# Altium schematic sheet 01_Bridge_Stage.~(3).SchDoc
size A4; SheetNumber: 3; SheetTotal: 3
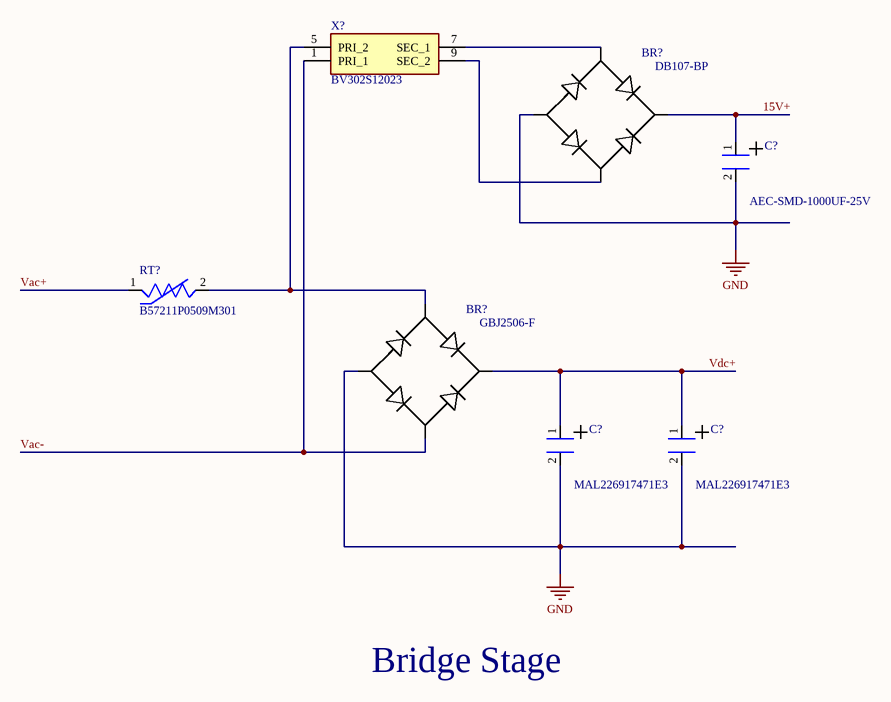
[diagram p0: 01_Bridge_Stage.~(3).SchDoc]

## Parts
(Parts that share a designator on the sheet are numbered #1, #2 ... from top to bottom, then left to right.)
BR?#1  DB107-BP  [898_DB107-BP]
BR?#2  GBJ2506-F  [996_GBJ_1]
C?#1  AEC-SMD-1000UF-25V  [098_AEC-SMD-1000UF-25V]
C?#2  MAL226917471E3  [099_MAL226917471E3]
C?#3  MAL226917471E3  [099_MAL226917471E3]
RT?  B57211P0509M301  [307_THRMRB750W80L1300T600H2000]
X?  BV302S12023  [899_BV302S12023]

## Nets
GND: BR?#1.2 BR?#2.4 C?#1.2 C?#2.2 C?#3.2
15V+: BR?#1.1 C?#1.1
Vac+: RT?.1
Vac-: BR?#2.3 X?.1(PRI_1)
Vdc+: BR?#2.1 C?#2.1 C?#3.1
NetBR?#1_3: BR?#1.3 X?.7(SEC_1)
NetBR?#1_4: BR?#1.4 X?.9(SEC_2)
NetBR?#2_2: BR?#2.2 RT?.2 X?.5(PRI_2)

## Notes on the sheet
- Bridge Stage

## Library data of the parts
BR?#1 = DB107-BP: Description; Manufacturer_Name: MCC
BR?#2 = GBJ2506-F: Bridge Rectifier; Manufacturer_Name: Diodes Incorporated
C?#1 = AEC-SMD-1000UF-25V: 1000 µF, 25 V polarized aluminum electrolytic capacitor, SMD V-chip package, Ø10 mm body, approx. 10.5 mm height, 105 °C rated.
C?#2 C?#3 = MAL226917471E3: 470 µF, 450 V polarized aluminum electrolytic capacitor, snap-in THT, Ø35 mm body, 10 mm lead spacing, 105 °C rated.
RT? = B57211P0509M301: Inrush Current Limiter 5 Ohms Â±20% 5 A 0.512 (13.00mm); MF: EPCOS
X? = BV302S12023: 2.3VA Encapsulated Transformer 50/60Hz; Manufacturer_Name: Zettler Group; Geometry.Height: 29.8mm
